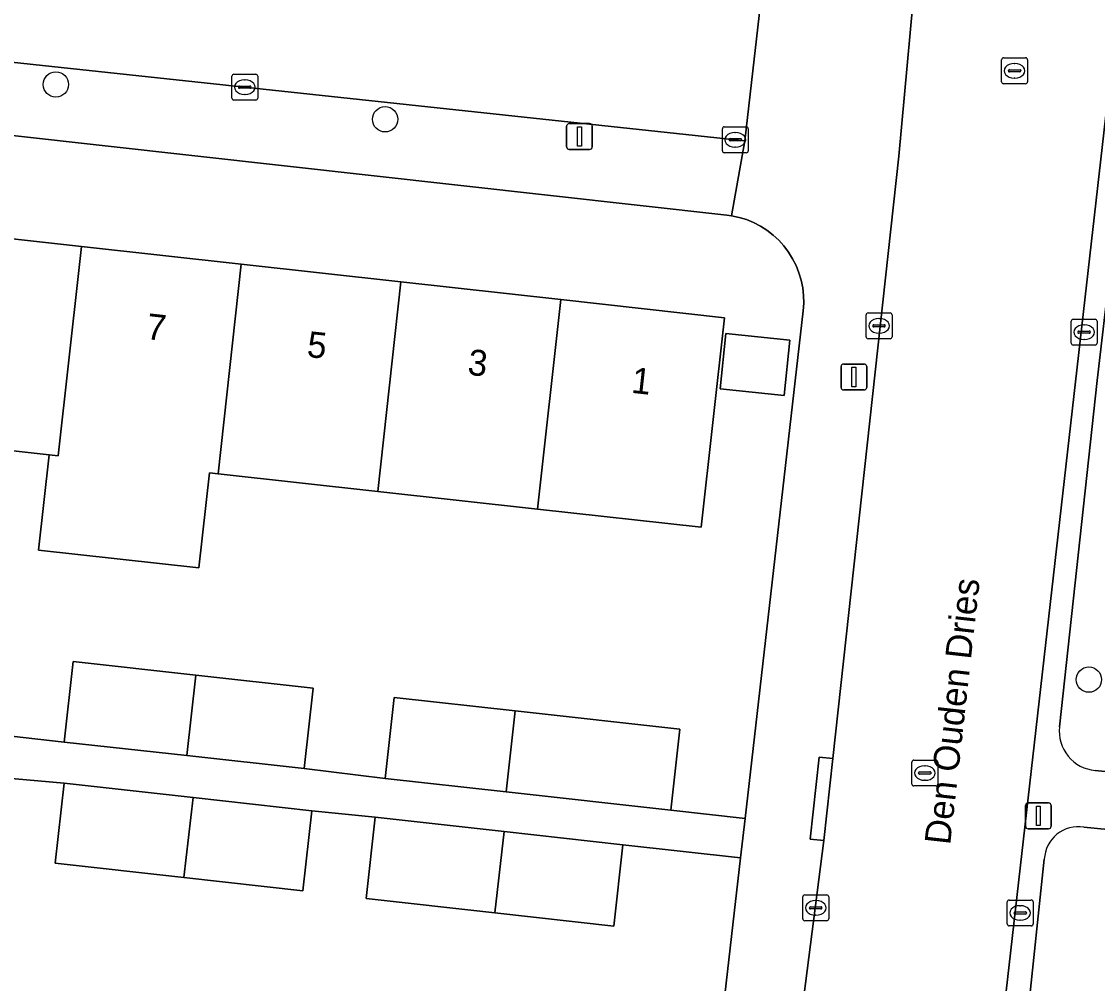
# Model space of a CAD drawing. Extents: x 162026 to 163502, y 387295 to 388169.
# Drawn here: x 162544.11 to 162585.7, y 387400.44 to 387437.62 of the extents above; entities that cross this region are included whole.
import ezdxf

# ---------------------------------------------------------------- set-up
doc = ezdxf.new("R2010")
doc.units = 0
for name, color, linetype in [('IMGEO_Boom', 7, 'Continuous'), ('IMGEO_Erf', 7, 'Continuous'), ('IMGEO_Groenvoorziening', 7, 'Continuous'), ('IMGEO_Kolk', 7, 'Continuous'), ('IMGEO_Lichtmast', 7, 'Continuous'), ('IMGEO_Openbare_ruimte_label', 7, 'Continuous'), ('IMGEO_Pand', 7, 'Continuous'), ('IMGEO_Pand_nummerreeks', 7, 'Continuous'), ('IMGEO_Rijbaan_lokaal_open', 7, 'Continuous'), ('IMGEO_Rioolput', 7, 'Continuous'), ('IMGEO_Voetpad_open', 7, 'Continuous')]:
    doc.layers.add(name, color=color, linetype=linetype)

msp = doc.modelspace()

# ---------------------------------------------------------------- linework, layer by layer
at = {"layer": 'IMGEO_Boom'}
for centre in [(162545.435, 387435.185), (162558.161, 387433.839), (162585.365, 387412.186)]:
    msp.add_circle(centre, 0.489, dxfattribs=at)
at = {"layer": 'IMGEO_Erf'}
for points in [[(162542.684, 387410.115), (162545.757, 387409.774), (162546.101, 387412.882), (162550.841, 387412.357), (162555.379, 387411.854), (162555.035, 387408.747), (162558.16, 387408.367), (162558.509, 387411.498), (162563.191, 387410.976), (162569.557, 387410.267), (162569.208, 387407.136), (162572.075, 387406.817), (162574.319, 387426.435), (162574.34, 387426.733), (162574.334, 387427.032), (162574.301, 387427.328), (162574.243, 387427.621), (162574.158, 387427.908), (162574.048, 387428.185), (162573.913, 387428.452), (162573.756, 387428.705), (162573.576, 387428.944), (162573.376, 387429.165), (162573.156, 387429.368), (162572.92, 387429.551), (162572.668, 387429.711), (162572.403, 387429.848), (162572.126, 387429.961), (162571.841, 387430.049), (162571.549, 387430.111), (162571.372, 387430.136), (162530.112, 387434.728)], [(162569.106, 387380.869), (162571.901, 387405.298), (162567.349, 387405.805), (162566.998, 387402.656), (162562.402, 387403.168), (162557.425, 387403.722), (162557.776, 387406.872), (162555.331, 387407.118), (162554.986, 387404.025), (162550.387, 387404.537), (162545.41, 387405.091), (162545.755, 387408.185), (162543.287, 387408.404), (162542.951, 387405.396), (162538.318, 387405.912), (162533.341, 387406.466), (162533.676, 387409.475), (162531.547, 387409.808), (162531.202, 387406.697), (162526.258, 387407.245), (162521.503, 387407.772), (162521.848, 387410.882), (162517.916, 387411.315), (162514.853, 387383.996)]]:
    msp.add_lwpolyline(points, dxfattribs=at)
for points in [[(162545.175, 387420.868), (162539.352, 387421.513), (162533.177, 387422.197), (162527.002, 387422.881), (162520.68, 387423.581), (162521.577, 387431.675), (162527.898, 387430.975), (162534.074, 387430.291), (162540.249, 387429.607), (162546.423, 387428.924), (162552.599, 387428.24), (162558.774, 387427.556), (162564.95, 387426.872), (162571.275, 387426.172), (162570.378, 387418.077), (162564.054, 387418.777), (162557.878, 387419.461), (162551.703, 387420.145), (162551.367, 387420.182), (162550.959, 387416.507), (162544.768, 387417.193)], [(162571.11, 387423.428), (162571.333, 387425.559), (162573.811, 387425.301), (162573.588, 387423.169)]]:
    msp.add_lwpolyline(points, close=True, dxfattribs=at)
at = {"layer": 'IMGEO_Groenvoorziening'}
for points in [[(162587.19, 387436.657), (162585.689, 387423.751), (162584.225, 387410.364)], [(162585.607, 387408.675), (162591.321, 387408.112)], [(162590.861, 387405.926), (162585.164, 387406.489)], [(162583.642, 387405.25), (162583.009, 387399.251), (162581.905, 387389.398), (162580.851, 387382.351), (162589.632, 387381.244), (162590.457, 387387.676), (162592.109, 387404.107)]]:
    msp.add_lwpolyline(points, dxfattribs=at)
for centre, radius, start, end in [((162585.747, 387410.199), 1.53, 173.8148, 264.7677), ((162584.964, 387405.181), 1.324, 81.2979, 176.9975)]:
    msp.add_arc(centre, radius, start, end, dxfattribs=at)
at = {"layer": 'IMGEO_Kolk'}
for p, q in [((162552.237, 387434.655), (162552.237, 387435.507)), ((162552.312, 387435.581), (162553.164, 387435.581)), ((162553.238, 387435.507), (162553.238, 387434.655)), ((162552.496, 387435.075), (162552.496, 387435.087)), ((162552.934, 387435.038), (162552.536, 387435.038)), ((162552.539, 387435.124), (162552.937, 387435.124)), ((162552.725, 387435.361), (162552.75, 387435.361)), ((162552.98, 387435.087), (162552.98, 387435.075)), ((162552.748, 387434.801), (162552.723, 387434.801)), ((162553.164, 387434.581), (162552.312, 387434.581)), ((162571.196, 387432.622), (162571.196, 387433.474)), ((162571.271, 387433.548), (162572.123, 387433.548)), ((162572.197, 387433.474), (162572.197, 387432.622)), ((162571.455, 387433.042), (162571.455, 387433.054)), ((162571.893, 387433.005), (162571.495, 387433.005)), ((162571.498, 387433.091), (162571.896, 387433.091)), ((162571.684, 387433.328), (162571.709, 387433.328)), ((162571.939, 387433.054), (162571.939, 387433.042)), ((162572.123, 387432.548), (162571.271, 387432.548)), ((162571.707, 387432.768), (162571.682, 387432.768)), ((162576.828, 387426.358), (162577.68, 387426.358)), ((162576.753, 387425.432), (162576.753, 387426.284)), ((162577.055, 387425.901), (162577.453, 387425.901)), ((162577.241, 387426.138), (162577.266, 387426.138)), ((162577.754, 387426.284), (162577.754, 387425.432)), ((162584.679, 387425.187), (162584.679, 387426.039)), ((162584.754, 387426.113), (162585.606, 387426.113)), ((162585.167, 387425.893), (162585.192, 387425.893)), ((162585.68, 387426.039), (162585.68, 387425.187)), ((162577.012, 387425.852), (162577.012, 387425.864)), ((162577.45, 387425.815), (162577.052, 387425.815)), ((162577.264, 387425.578), (162577.239, 387425.578)), ((162577.496, 387425.864), (162577.496, 387425.852)), ((162584.938, 387425.607), (162584.938, 387425.619)), ((162585.376, 387425.57), (162584.978, 387425.57)), ((162584.981, 387425.656), (162585.379, 387425.656)), ((162585.422, 387425.619), (162585.422, 387425.607)), ((162577.68, 387425.358), (162576.828, 387425.358)), ((162585.606, 387425.113), (162584.754, 387425.113)), ((162585.19, 387425.333), (162585.165, 387425.333)), ((162574.38, 387403.866), (162575.232, 387403.866)), ((162574.305, 387402.94), (162574.305, 387403.792)), ((162574.793, 387403.646), (162574.818, 387403.646)), ((162575.306, 387403.792), (162575.306, 387402.94)), ((162582.211, 387402.744), (162582.211, 387403.596)), ((162582.286, 387403.67), (162583.138, 387403.67)), ((162582.699, 387403.45), (162582.724, 387403.45)), ((162583.212, 387403.596), (162583.212, 387402.744)), ((162574.564, 387403.36), (162574.564, 387403.372)), ((162575.002, 387403.323), (162574.604, 387403.323)), ((162574.607, 387403.409), (162575.005, 387403.409)), ((162574.816, 387403.086), (162574.791, 387403.086)), ((162575.048, 387403.372), (162575.048, 387403.36)), ((162582.47, 387403.164), (162582.47, 387403.176)), ((162582.908, 387403.127), (162582.51, 387403.127)), ((162582.513, 387403.213), (162582.911, 387403.213)), ((162582.954, 387403.176), (162582.954, 387403.164)), ((162575.232, 387402.866), (162574.38, 387402.866)), ((162583.138, 387402.67), (162582.286, 387402.67)), ((162582.722, 387402.89), (162582.697, 387402.89))]:
    msp.add_line(p, q, dxfattribs=at)
for points in [[(162552.237, 387434.655), (162552.237, 387435.507)], [(162552.312, 387435.581), (162553.164, 387435.581)], [(162553.238, 387435.507), (162553.238, 387434.655)], [(162553.164, 387434.581), (162552.312, 387434.581)], [(162571.196, 387432.622), (162571.196, 387433.474)], [(162571.271, 387433.548), (162572.123, 387433.548)], [(162572.197, 387433.474), (162572.197, 387432.622)], [(162572.123, 387432.548), (162571.271, 387432.548)], [(162576.828, 387426.358), (162577.68, 387426.358)], [(162576.753, 387425.432), (162576.753, 387426.284)], [(162577.754, 387426.284), (162577.754, 387425.432)], [(162584.679, 387425.187), (162584.679, 387426.039)], [(162584.754, 387426.113), (162585.606, 387426.113)], [(162585.68, 387426.039), (162585.68, 387425.187)], [(162577.68, 387425.358), (162576.828, 387425.358)], [(162585.606, 387425.113), (162584.754, 387425.113)], [(162574.38, 387403.866), (162575.232, 387403.866)], [(162574.305, 387402.94), (162574.305, 387403.792)], [(162575.306, 387403.792), (162575.306, 387402.94)], [(162582.211, 387402.744), (162582.211, 387403.596)], [(162582.286, 387403.67), (162583.138, 387403.67)], [(162583.212, 387403.596), (162583.212, 387402.744)], [(162575.232, 387402.866), (162574.38, 387402.866)], [(162583.138, 387402.67), (162582.286, 387402.67)]]:
    msp.add_lwpolyline(points, dxfattribs=at)
for centre, radius, start, end in [((162552.314, 387435.505), 0.0765, 91.552, 178.448), ((162552.314, 387435.505), 0.0765, 91.552, 178.448), ((162553.162, 387435.505), 0.0765, 1.552, 88.448), ((162553.162, 387435.505), 0.0765, 1.552, 88.448), ((162552.536, 387435.084), 0.0403, 85.8775, 175.7526), ((162552.533, 387435.074), 0.0366, 178.938, 274.7102), ((162552.937, 387435.081), 0.043, 264.8664, 352.4533), ((162552.941, 387435.086), 0.0386, 1.7309, 96.639), ((162552.314, 387434.657), 0.0765, 181.552, 268.448), ((162552.314, 387434.657), 0.0765, 181.552, 268.448), ((162553.162, 387434.657), 0.0765, 271.552, 358.448), ((162553.162, 387434.657), 0.0765, 271.552, 358.448), ((162571.273, 387433.472), 0.0765, 91.552, 178.448), ((162571.273, 387433.472), 0.0765, 91.552, 178.448), ((162572.121, 387433.472), 0.0765, 1.552, 88.448), ((162572.121, 387433.472), 0.0765, 1.552, 88.448), ((162571.495, 387433.051), 0.0403, 85.8775, 175.7526), ((162571.492, 387433.041), 0.0366, 178.938, 274.7102), ((162571.896, 387433.048), 0.043, 264.8664, 352.4533), ((162571.9, 387433.053), 0.0386, 1.7309, 96.639), ((162571.273, 387432.624), 0.0765, 181.552, 268.448), ((162571.273, 387432.624), 0.0765, 181.552, 268.448), ((162572.121, 387432.624), 0.0765, 271.552, 358.448), ((162572.121, 387432.624), 0.0765, 271.552, 358.448), ((162576.83, 387426.282), 0.0765, 91.552, 178.448), ((162576.83, 387426.282), 0.0765, 91.552, 178.448), ((162577.678, 387426.282), 0.0765, 1.552, 88.448), ((162577.678, 387426.282), 0.0765, 1.552, 88.448), ((162577.052, 387425.861), 0.0403, 85.8775, 175.7526), ((162577.457, 387425.863), 0.0386, 1.7309, 96.639), ((162584.756, 387426.037), 0.0765, 91.552, 178.448), ((162584.756, 387426.037), 0.0765, 91.552, 178.448), ((162585.604, 387426.037), 0.0765, 1.552, 88.448), ((162585.604, 387426.037), 0.0765, 1.552, 88.448), ((162577.049, 387425.851), 0.0366, 178.938, 274.7102), ((162577.453, 387425.858), 0.043, 264.8664, 352.4533), ((162584.978, 387425.616), 0.0403, 85.8775, 175.7526), ((162584.975, 387425.606), 0.0366, 178.938, 274.7102), ((162585.379, 387425.613), 0.043, 264.8664, 352.4533), ((162585.383, 387425.618), 0.0386, 1.7309, 96.639), ((162576.83, 387425.434), 0.0765, 181.552, 268.448), ((162576.83, 387425.434), 0.0765, 181.552, 268.448), ((162577.678, 387425.434), 0.0765, 271.552, 358.448), ((162577.678, 387425.434), 0.0765, 271.552, 358.448), ((162584.756, 387425.189), 0.0765, 181.552, 268.448), ((162584.756, 387425.189), 0.0765, 181.552, 268.448), ((162585.604, 387425.189), 0.0765, 271.552, 358.448), ((162585.604, 387425.189), 0.0765, 271.552, 358.448), ((162574.382, 387403.79), 0.0765, 91.552, 178.448), ((162574.382, 387403.79), 0.0765, 91.552, 178.448), ((162575.23, 387403.79), 0.0765, 1.552, 88.448), ((162575.23, 387403.79), 0.0765, 1.552, 88.448), ((162582.288, 387403.594), 0.0765, 91.552, 178.448), ((162582.288, 387403.594), 0.0765, 91.552, 178.448), ((162583.136, 387403.594), 0.0765, 1.552, 88.448), ((162583.136, 387403.594), 0.0765, 1.552, 88.448), ((162574.604, 387403.369), 0.0403, 85.8775, 175.7526), ((162574.601, 387403.359), 0.0366, 178.938, 274.7102), ((162575.005, 387403.366), 0.043, 264.8664, 352.4533), ((162575.009, 387403.371), 0.0386, 1.7309, 96.639), ((162582.51, 387403.173), 0.0403, 85.8775, 175.7526), ((162582.507, 387403.163), 0.0366, 178.938, 274.7102), ((162582.911, 387403.17), 0.043, 264.8664, 352.4533), ((162582.915, 387403.175), 0.0386, 1.7309, 96.639), ((162574.382, 387402.942), 0.0765, 181.552, 268.448), ((162574.382, 387402.942), 0.0765, 181.552, 268.448), ((162575.23, 387402.942), 0.0765, 271.552, 358.448), ((162575.23, 387402.942), 0.0765, 271.552, 358.448), ((162582.288, 387402.746), 0.0765, 181.552, 268.448), ((162582.288, 387402.746), 0.0765, 181.552, 268.448), ((162583.136, 387402.746), 0.0765, 271.552, 358.448), ((162583.136, 387402.746), 0.0765, 271.552, 358.448)]:
    msp.add_arc(centre, radius, start, end, dxfattribs=at)
for centre, major_axis, ratio, start_param, end_param in [((162552.724, 387435.081), (-0.387, 0.002), 0.722429, 4.712389, 7.853982), ((162552.749, 387435.081), (-0.39, 0.002), 0.717154, 1.570796, 4.712389), ((162571.683, 387433.048), (-0.387, 0.002), 0.722429, 4.712389, 7.853982), ((162571.708, 387433.048), (-0.39, 0.002), 0.717154, 1.570796, 4.712389), ((162577.24, 387425.858), (-0.387, 0.002), 0.722429, 4.712389, 7.853982), ((162577.265, 387425.858), (-0.39, 0.002), 0.717154, 1.570796, 4.712389), ((162585.166, 387425.613), (-0.387, 0.002), 0.722429, 4.712389, 7.853982), ((162585.191, 387425.613), (-0.39, 0.002), 0.717154, 1.570796, 4.712389), ((162574.792, 387403.366), (-0.387, 0.002), 0.722429, 4.712389, 7.853982), ((162574.817, 387403.366), (-0.39, 0.002), 0.717154, 1.570796, 4.712389), ((162582.698, 387403.17), (-0.387, 0.002), 0.722429, 4.712389, 7.853982), ((162582.723, 387403.17), (-0.39, 0.002), 0.717154, 1.570796, 4.712389)]:
    msp.add_ellipse(centre, major_axis=major_axis, ratio=ratio, start_param=start_param, end_param=end_param, dxfattribs=at)
at = {"layer": 'IMGEO_Lichtmast'}
for p, q in [((162565.177, 387432.772), (162565.177, 387433.572)), ((162565.177, 387433.572), (162565.177, 387432.772)), ((162565.277, 387433.672), (162566.067, 387433.672)), ((162566.067, 387433.672), (162565.277, 387433.672)), ((162566.167, 387433.572), (162566.167, 387432.772)), ((162566.167, 387432.772), (162566.167, 387433.572)), ((162566.067, 387432.672), (162565.277, 387432.672)), ((162565.277, 387432.672), (162566.067, 387432.672)), ((162575.786, 387423.48), (162575.786, 387424.28)), ((162575.786, 387424.28), (162575.786, 387423.48)), ((162575.886, 387424.38), (162576.676, 387424.38)), ((162576.676, 387424.38), (162575.886, 387424.38)), ((162576.776, 387424.28), (162576.776, 387423.48)), ((162576.776, 387423.48), (162576.776, 387424.28)), ((162576.676, 387423.38), (162575.886, 387423.38)), ((162575.886, 387423.38), (162576.676, 387423.38)), ((162582.917, 387406.522), (162582.917, 387407.322)), ((162582.917, 387407.322), (162582.917, 387406.522)), ((162583.017, 387407.422), (162583.807, 387407.422)), ((162583.807, 387407.422), (162583.017, 387407.422)), ((162583.907, 387407.322), (162583.907, 387406.522)), ((162583.907, 387406.522), (162583.907, 387407.322)), ((162583.807, 387406.422), (162583.017, 387406.422)), ((162583.017, 387406.422), (162583.807, 387406.422))]:
    msp.add_line(p, q, dxfattribs=at)
for points in [[(162565.597, 387433.547), (162565.747, 387433.547), (162565.747, 387432.797), (162565.597, 387432.797), (162565.597, 387433.547)], [(162576.206, 387424.255), (162576.356, 387424.255), (162576.356, 387423.505), (162576.206, 387423.505), (162576.206, 387424.255)], [(162583.337, 387407.297), (162583.487, 387407.297), (162583.487, 387406.547), (162583.337, 387406.547), (162583.337, 387407.297)]]:
    msp.add_lwpolyline(points, dxfattribs=at)
for centre, start, end in [((162565.277, 387433.572), 90, 180), ((162565.277, 387433.572), 90, 180), ((162566.067, 387433.572), 0, 90), ((162566.067, 387433.572), 360, 90), ((162565.277, 387432.772), 180, 270), ((162565.277, 387432.772), 180, 270), ((162566.067, 387432.772), 270, 0), ((162566.067, 387432.772), 270, 0), ((162575.886, 387424.28), 90, 180), ((162575.886, 387424.28), 90, 180), ((162576.676, 387424.28), 0, 90), ((162576.676, 387424.28), 360, 90), ((162575.886, 387423.48), 180, 270), ((162575.886, 387423.48), 180, 270), ((162576.676, 387423.48), 270, 0), ((162576.676, 387423.48), 270, 0), ((162583.017, 387407.322), 90, 180), ((162583.017, 387407.322), 90, 180), ((162583.807, 387407.322), 0, 90), ((162583.807, 387407.322), 360, 90), ((162583.017, 387406.522), 180, 270), ((162583.017, 387406.522), 180, 270), ((162583.807, 387406.522), 270, 0), ((162583.807, 387406.522), 270, 0)]:
    msp.add_arc(centre, 0.1, start, end, dxfattribs=at)
at = {"layer": 'IMGEO_Pand'}
for points in [[(162546.334, 387428.117), (162546.423, 387428.924), (162540.249, 387429.607), (162539.352, 387421.513), (162545.175, 387420.868), (162545.528, 387420.829)], [(162552.599, 387428.24), (162546.423, 387428.924), (162546.334, 387428.117), (162545.528, 387420.829), (162545.175, 387420.868), (162544.768, 387417.193), (162550.959, 387416.507), (162551.367, 387420.182), (162551.703, 387420.145)], [(162558.774, 387427.556), (162552.599, 387428.24), (162551.703, 387420.145), (162557.878, 387419.461)], [(162557.878, 387419.461), (162564.054, 387418.777), (162564.95, 387426.872), (162558.774, 387427.556)], [(162564.054, 387418.777), (162570.378, 387418.077), (162571.275, 387426.172), (162564.95, 387426.872)], [(162573.588, 387423.169), (162573.811, 387425.301), (162571.333, 387425.559), (162571.11, 387423.428)], [(162546.101, 387412.882), (162545.757, 387409.774), (162550.497, 387409.249), (162550.841, 387412.357)], [(162555.035, 387408.747), (162555.379, 387411.854), (162550.841, 387412.357), (162550.497, 387409.249)], [(162563.191, 387410.976), (162558.509, 387411.498), (162558.16, 387408.367), (162562.844, 387407.845)], [(162562.844, 387407.845), (162569.208, 387407.136), (162569.557, 387410.267), (162563.191, 387410.976)], [(162550.74, 387407.629), (162545.755, 387408.185), (162545.41, 387405.091), (162550.387, 387404.537)], [(162550.387, 387404.537), (162554.986, 387404.025), (162555.331, 387407.118), (162550.74, 387407.629)], [(162562.761, 387406.316), (162557.776, 387406.872), (162557.425, 387403.722), (162562.402, 387403.168)], [(162562.402, 387403.168), (162566.998, 387402.656), (162567.349, 387405.805), (162562.761, 387406.316)]]:
    msp.add_lwpolyline(points, close=True, dxfattribs=at)
at = {"layer": 'IMGEO_Rijbaan_lokaal_open'}
for points in [[(162540.563, 387448.199), (162537.24, 387469.944), (162537.082, 387470.994), (162536.24, 387476.571), (162528.88, 387477.412), (162531.114, 387463.071), (162535.182, 387436.966), (162572.06, 387433.011), (162572.882, 387440.121), (162572.776, 387440.133), (162546.338, 387443.004)], [(162586.67, 387439.788), (162578.784, 387440.7), (162578.017, 387432.414), (162575.462, 387409.143), (162575.114, 387405.97), (162572.612, 387386.379), (162572.427, 387384.787), (162572.068, 387382.025)], [(162573.722, 387378.713), (162579.655, 387378.051), (162580.172, 387382.561), (162580.231, 387383.076), (162580.451, 387385.092), (162586.67, 387439.788)]]:
    msp.add_lwpolyline(points, dxfattribs=at)
at = {"layer": 'IMGEO_Rioolput'}
for p, q in [((162581.992, 387435.288), (162581.992, 387436.14)), ((162582.067, 387436.214), (162582.919, 387436.214)), ((162582.48, 387435.994), (162582.505, 387435.994)), ((162582.993, 387436.14), (162582.993, 387435.288)), ((162582.251, 387435.708), (162582.251, 387435.72)), ((162582.689, 387435.671), (162582.291, 387435.671)), ((162582.294, 387435.757), (162582.692, 387435.757)), ((162582.735, 387435.72), (162582.735, 387435.708)), ((162582.919, 387435.214), (162582.067, 387435.214)), ((162582.503, 387435.434), (162582.478, 387435.434)), ((162578.521, 387408.15), (162578.521, 387409.002)), ((162578.596, 387409.076), (162579.448, 387409.076)), ((162579.009, 387408.856), (162579.034, 387408.856)), ((162579.522, 387409.002), (162579.522, 387408.15)), ((162578.78, 387408.57), (162578.78, 387408.582)), ((162579.218, 387408.533), (162578.82, 387408.533)), ((162578.823, 387408.619), (162579.221, 387408.619)), ((162579.264, 387408.582), (162579.264, 387408.57)), ((162579.448, 387408.076), (162578.596, 387408.076)), ((162579.032, 387408.296), (162579.007, 387408.296))]:
    msp.add_line(p, q, dxfattribs=at)
for points in [[(162581.992, 387435.288), (162581.992, 387436.14)], [(162582.067, 387436.214), (162582.919, 387436.214)], [(162582.993, 387436.14), (162582.993, 387435.288)], [(162582.919, 387435.214), (162582.067, 387435.214)], [(162578.521, 387408.15), (162578.521, 387409.002)], [(162578.596, 387409.076), (162579.448, 387409.076)], [(162579.522, 387409.002), (162579.522, 387408.15)], [(162579.448, 387408.076), (162578.596, 387408.076)]]:
    msp.add_lwpolyline(points, dxfattribs=at)
for centre, radius, start, end in [((162582.069, 387436.138), 0.0765, 91.552, 178.448), ((162582.069, 387436.138), 0.0765, 91.552, 178.448), ((162582.917, 387436.138), 0.0765, 1.552, 88.448), ((162582.917, 387436.138), 0.0765, 1.552, 88.448), ((162582.291, 387435.717), 0.0403, 85.8775, 175.7526), ((162582.288, 387435.707), 0.0366, 178.938, 274.7102), ((162582.692, 387435.714), 0.043, 264.8664, 352.4533), ((162582.696, 387435.719), 0.0386, 1.7309, 96.639), ((162582.069, 387435.29), 0.0765, 181.552, 268.448), ((162582.069, 387435.29), 0.0765, 181.552, 268.448), ((162582.917, 387435.29), 0.0765, 271.552, 358.448), ((162582.917, 387435.29), 0.0765, 271.552, 358.448), ((162578.598, 387409), 0.0765, 91.552, 178.448), ((162578.598, 387409), 0.0765, 91.552, 178.448), ((162579.446, 387409), 0.0765, 1.552, 88.448), ((162579.446, 387409), 0.0765, 1.552, 88.448), ((162578.82, 387408.579), 0.0403, 85.8775, 175.7526), ((162578.817, 387408.569), 0.0366, 178.938, 274.7102), ((162579.221, 387408.576), 0.043, 264.8664, 352.4533), ((162579.225, 387408.581), 0.0386, 1.7309, 96.639), ((162578.598, 387408.152), 0.0765, 181.552, 268.448), ((162578.598, 387408.152), 0.0765, 181.552, 268.448), ((162579.446, 387408.152), 0.0765, 271.552, 358.448), ((162579.446, 387408.152), 0.0765, 271.552, 358.448)]:
    msp.add_arc(centre, radius, start, end, dxfattribs=at)
for centre, major_axis, ratio, start_param, end_param in [((162582.479, 387435.714), (-0.387, 0.002), 0.722429, 4.712389, 7.853982), ((162582.504, 387435.714), (-0.39, 0.002), 0.717154, 1.570796, 4.712389), ((162579.008, 387408.576), (-0.387, 0.002), 0.722429, 4.712389, 7.853982), ((162579.033, 387408.576), (-0.39, 0.002), 0.717154, 1.570796, 4.712389)]:
    msp.add_ellipse(centre, major_axis=major_axis, ratio=ratio, start_param=start_param, end_param=end_param, dxfattribs=at)
at = {"layer": 'IMGEO_Voetpad_open'}
for points in [[(162589.807, 387467.375), (162587.09, 387443.478), (162586.67, 387439.788), (162580.451, 387385.092), (162580.231, 387383.076), (162580.172, 387382.561), (162579.655, 387378.051), (162579.504, 387376.706), (162581.714, 387376.483)], [(162578.017, 387432.414), (162578.784, 387440.7), (162579.124, 387444.366), (162579.275, 387445.939)], [(162572.882, 387440.121), (162572.06, 387433.011), (162571.549, 387430.111), (162571.841, 387430.049), (162572.126, 387429.961), (162572.403, 387429.848), (162572.668, 387429.711), (162572.92, 387429.551), (162573.156, 387429.368), (162573.376, 387429.165), (162573.576, 387428.944), (162573.756, 387428.705), (162573.913, 387428.452), (162574.048, 387428.185), (162574.158, 387427.908), (162574.243, 387427.621), (162574.301, 387427.328), (162574.334, 387427.032), (162574.34, 387426.733), (162574.319, 387426.435), (162572.075, 387406.817), (162571.901, 387405.298), (162569.106, 387380.869)], [(162584.225, 387410.364), (162585.689, 387423.751), (162587.19, 387436.657)], [(162572.068, 387382.025), (162572.427, 387384.787), (162572.612, 387386.379), (162575.114, 387405.97), (162574.594, 387406.023), (162574.939, 387409.196), (162575.462, 387409.143), (162578.017, 387432.414)], [(162543.287, 387408.404), (162545.755, 387408.185), (162550.74, 387407.629), (162555.331, 387407.118), (162557.776, 387406.872), (162562.761, 387406.316), (162567.349, 387405.805), (162571.901, 387405.298), (162572.075, 387406.817), (162569.208, 387407.136), (162562.844, 387407.845), (162558.16, 387408.367), (162555.035, 387408.747), (162550.497, 387409.249), (162545.757, 387409.774), (162542.684, 387410.115)], [(162591.321, 387408.112), (162585.607, 387408.675)], [(162585.164, 387406.489), (162590.861, 387405.926)], [(162580.321, 387378.255), (162580.411, 387379.412), (162580.851, 387382.351), (162581.905, 387389.398), (162583.009, 387399.251), (162583.642, 387405.25)]]:
    msp.add_lwpolyline(points, dxfattribs=at)
for points in [[(162535.182, 387436.966), (162530.432, 387437.605), (162530.112, 387434.728), (162571.372, 387430.136), (162571.549, 387430.111), (162572.06, 387433.011)], [(162575.462, 387409.143), (162574.939, 387409.196), (162574.594, 387406.023), (162575.114, 387405.97)]]:
    msp.add_lwpolyline(points, close=True, dxfattribs=at)
for centre, radius, start, end in [((162585.747, 387410.199), 1.53, 173.8148, 264.7677), ((162584.964, 387405.181), 1.324, 81.2979, 176.9975)]:
    msp.add_arc(centre, radius, start, end, dxfattribs=at)

# ---------------------------------------------------------------- texts
at = {"layer": 'IMGEO_Openbare_ruimte_label'}
msp.add_text('Den Ouden Dries', height=1, rotation=83.6282, dxfattribs=at).set_placement((162580.002, 387405.776))
at = {"layer": 'IMGEO_Pand_nummerreeks'}
for s, rotation, p in [('7', 353.6803, (162548.898, 387425.35)), ('5', 353.6814, (162555.109, 387424.662)), ('3', 353.6814, (162561.321, 387423.974)), ('1', 353.6814, (162567.648, 387423.274))]:
    msp.add_text(s, height=1, rotation=rotation, dxfattribs=at).set_placement(p)

doc.saveas('drawing.dxf')
